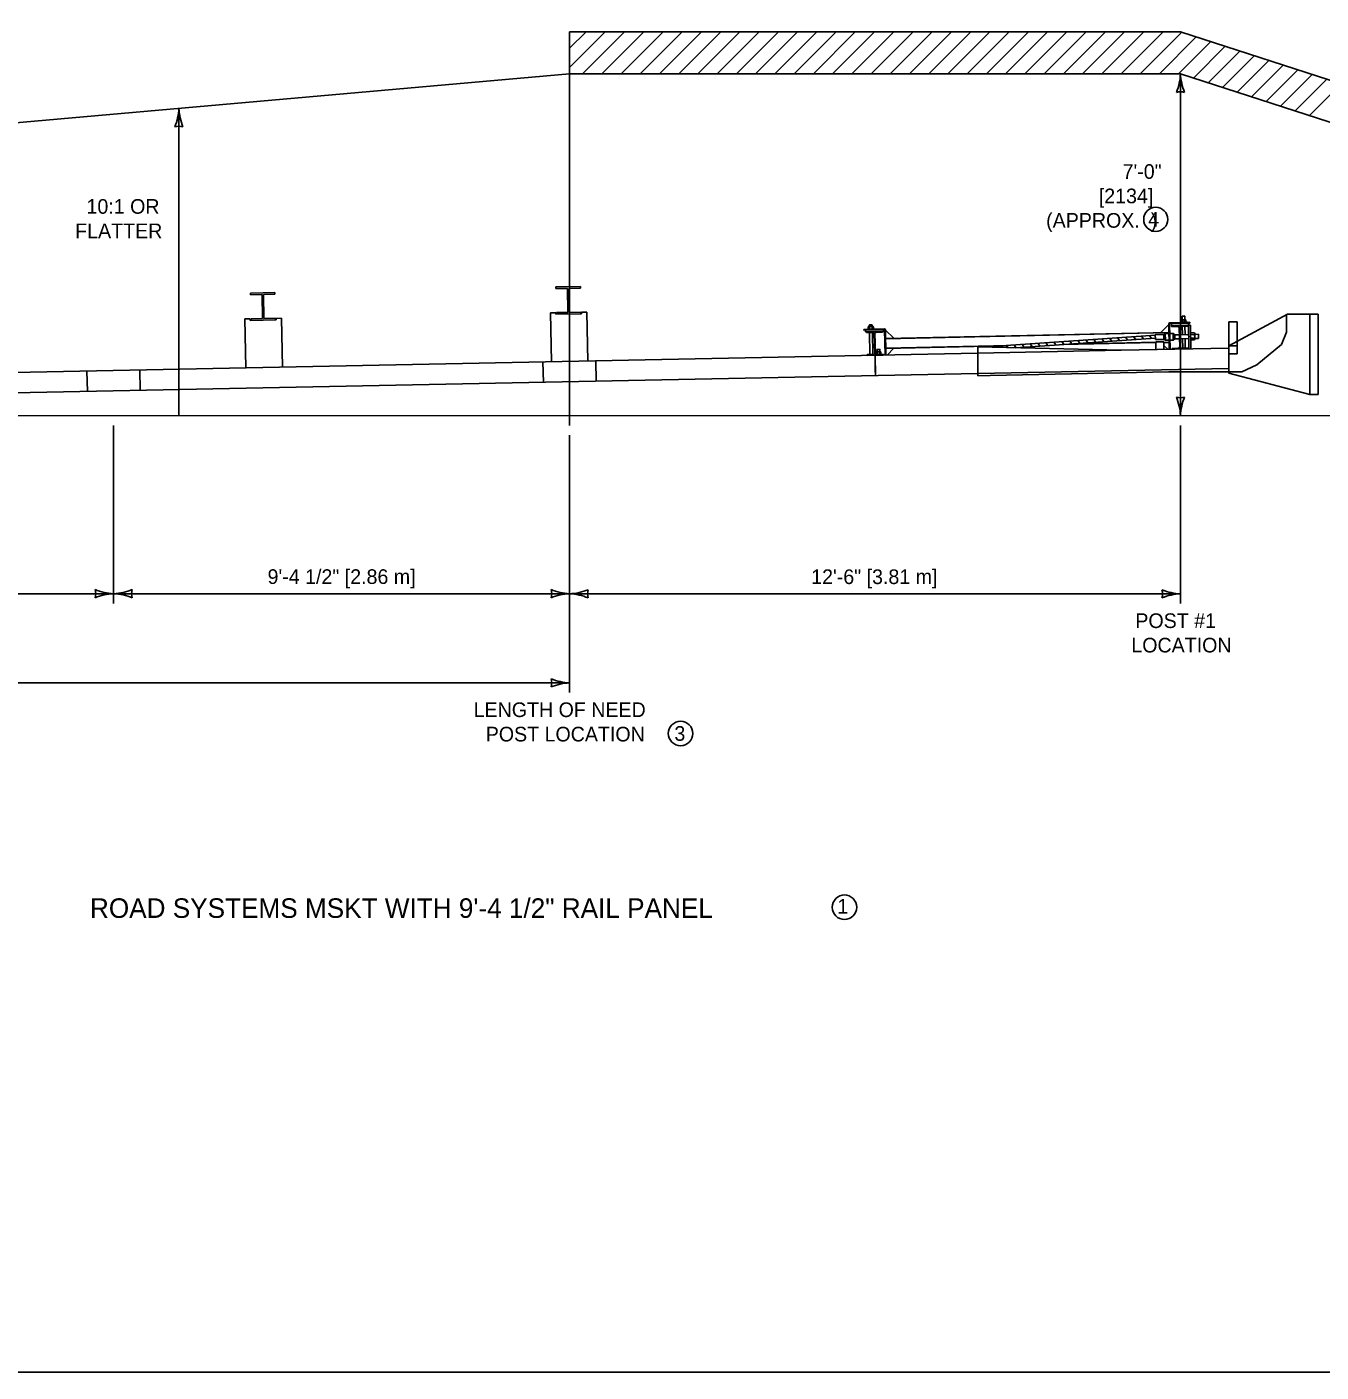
# Model space of a CAD drawing. Extents: x 49991.4 to 50021, y 49987.6 to 50011.4.
# Drawn here: x 50006.31 to 50011.61, y 49987.8 to 49993.3 of the extents above; entities that cross this region are included whole.
import ezdxf

# ---------------------------------------------------------------- set-up
doc = ezdxf.new("R2010")
doc.units = 0
for name, color, linetype in [('Level 1', 7, 'Continuous'), ('Level 2', 7, 'Continuous'), ('Level 3', 7, 'Continuous'), ('Level 5', 7, 'Continuous')]:
    doc.layers.add(name, color=color, linetype=linetype)

msp = doc.modelspace()

# ---------------------------------------------------------------- linework, layer by layer
at = {"layer": 'Level 1'}
for p, q in [((50011.0311, 49993.2847), (50008.5311, 49993.2847)), ((50008.5311, 49993.2847), (50008.5311, 49993.1129)), ((50008.6772, 49993.2847), (50008.5311, 49993.1386)), ((50008.5985, 49993.2847), (50008.5311, 49993.2173)), ((50008.7559, 49993.2847), (50008.5841, 49993.1129)), ((50008.8346, 49993.2847), (50008.6628, 49993.1129)), ((50008.9133, 49993.2847), (50008.7415, 49993.1129)), ((50008.992, 49993.2847), (50008.8202, 49993.1129)), ((50009.0707, 49993.2847), (50008.8989, 49993.1129)), ((50009.1494, 49993.2847), (50008.9776, 49993.1129)), ((50009.2281, 49993.2847), (50009.0563, 49993.1129)), ((50009.3068, 49993.2847), (50009.135, 49993.1129)), ((50009.3855, 49993.2847), (50009.2137, 49993.1129)), ((50009.4642, 49993.2847), (50009.2924, 49993.1129)), ((50009.5429, 49993.2847), (50009.3711, 49993.1129)), ((50009.6216, 49993.2847), (50009.4498, 49993.1129)), ((50009.7003, 49993.2847), (50009.5286, 49993.1129)), ((50009.779, 49993.2847), (50009.6073, 49993.1129)), ((50009.8577, 49993.2847), (50009.686, 49993.1129)), ((50009.9364, 49993.2847), (50009.7647, 49993.1129)), ((50010.0151, 49993.2847), (50009.8434, 49993.1129)), ((50010.0938, 49993.2847), (50009.9221, 49993.1129)), ((50010.1725, 49993.2847), (50010.0008, 49993.1129)), ((50010.2512, 49993.2847), (50010.0795, 49993.1129)), ((50010.3299, 49993.2847), (50010.1582, 49993.1129)), ((50010.4086, 49993.2847), (50010.2369, 49993.1129)), ((50010.4873, 49993.2847), (50010.3156, 49993.1129)), ((50010.5661, 49993.2847), (50010.3943, 49993.1129)), ((50010.6448, 49993.2847), (50010.473, 49993.1129)), ((50010.7235, 49993.2847), (50010.5517, 49993.1129)), ((50010.8022, 49993.2847), (50010.6304, 49993.1129)), ((50010.8809, 49993.2847), (50010.7091, 49993.1129)), ((50010.9596, 49993.2847), (50010.7878, 49993.1129)), ((50011.0365, 49993.2829), (50010.8665, 49993.1129)), ((50011.0959, 49993.2637), (50010.9451, 49993.1129)), ((50011.1552, 49993.2444), (50011.0236, 49993.1129)), ((50015.8765, 49991.7129), (50011.0311, 49993.2847)), ((50011.2144, 49993.2252), (50011.0848, 49993.0955)), ((50011.2738, 49993.206), (50011.1441, 49993.0763)), ((50011.3331, 49993.1867), (50011.2035, 49993.057)), ((50011.3924, 49993.1675), (50011.2628, 49993.0378)), ((50011.4518, 49993.1482), (50011.322, 49993.0186)), ((50011.5112, 49993.129), (50011.3814, 49992.9993)), ((50008.5311, 49993.1129), (50001.6559, 49992.504)), ((50011.0311, 49993.1129), (50008.5311, 49993.1129)), ((50015.3468, 49991.713), (50011.0311, 49993.1129)), ((50011.5704, 49993.1098), (50011.4407, 49992.98)), ((50011.6297, 49993.0905), (50011.5, 49992.9608)), ((50011.6891, 49993.0713), (50011.5594, 49992.9416)), ((50008.5749, 49992.2424), (50008.4752, 49992.2404)), ((50008.575, 49992.2356), (50008.5749, 49992.2424)), ((50007.3249, 49992.2174), (50007.2252, 49992.2154)), ((50007.2253, 49992.2086), (50007.2252, 49992.2154)), ((50007.2723, 49992.2095), (50007.2253, 49992.2086)), ((50007.2742, 49992.1112), (50007.2723, 49992.2095)), ((50007.325, 49992.2106), (50007.2781, 49992.2096)), ((50007.28, 49992.1113), (50007.2781, 49992.2096)), ((50007.325, 49992.2106), (50007.3249, 49992.2174)), ((50008.4753, 49992.2336), (50008.4752, 49992.2404)), ((50008.5223, 49992.2345), (50008.4753, 49992.2336)), ((50008.5242, 49992.1362), (50008.5223, 49992.2345)), ((50008.575, 49992.2356), (50008.5281, 49992.2346)), ((50008.53, 49992.1363), (50008.5281, 49992.2346)), ((50008.4523, 49992.1342), (50008.4742, 49992.1346)), ((50008.4523, 49992.1342), (50008.4563, 49991.9342)), ((50008.4742, 49992.1346), (50008.4743, 49992.1285)), ((50008.5242, 49992.1362), (50008.4773, 49992.1353)), ((50008.4774, 49992.1285), (50008.4773, 49992.1353)), ((50008.577, 49992.1373), (50008.53, 49992.1363)), ((50008.5771, 49992.1305), (50008.577, 49992.1373)), ((50008.58, 49992.1368), (50008.6018, 49992.1372)), ((50008.5801, 49992.1306), (50008.58, 49992.1368)), ((50008.6058, 49991.9372), (50008.6018, 49992.1372)), ((50007.2023, 49992.1092), (50007.2242, 49992.1096)), ((50007.2023, 49992.1092), (50007.2063, 49991.9092)), ((50007.2242, 49992.1096), (50007.2243, 49992.1035)), ((50007.3301, 49992.1056), (50007.2243, 49992.1035)), ((50007.2742, 49992.1112), (50007.2273, 49992.1103)), ((50007.2274, 49992.1035), (50007.2273, 49992.1103)), ((50007.327, 49992.1123), (50007.28, 49992.1113)), ((50007.3271, 49992.1055), (50007.327, 49992.1123)), ((50007.33, 49992.1118), (50007.3518, 49992.1122)), ((50007.3301, 49992.1056), (50007.33, 49992.1118)), ((50007.3558, 49991.9122), (50007.3518, 49992.1122)), ((50008.5801, 49992.1306), (50008.4743, 49992.1285)), ((50009.7528, 49992.0677), (50009.7526, 49992.0773)), ((50009.7716, 49992.0784), (50009.7553, 49992.0781)), ((50009.7582, 49992.0678), (50009.758, 49992.0774)), ((50009.7584, 49992.0853), (50009.7684, 49992.0855)), ((50009.7691, 49992.068), (50009.7689, 49992.0776)), ((50009.7745, 49992.0681), (50009.7743, 49992.0777)), ((50010.983, 49992.0866), (50010.9509, 49992.0538)), ((50010.985, 49991.9849), (50010.9829, 49992.0897)), ((50010.9861, 49992.0897), (50010.9882, 49991.985)), ((50010.987, 49992.0939), (50011.069, 49992.0955)), ((50010.9871, 49992.0908), (50011.069, 49992.0924)), ((50010.9945, 49992.0901), (50011.0634, 49992.0915)), ((50010.9947, 49992.0819), (50010.9945, 49992.0901)), ((50011.0636, 49992.0833), (50010.9947, 49992.0819)), ((50010.9947, 49992.0819), (50010.9947, 49992.0784)), ((50010.9947, 49992.0784), (50011.0204, 49992.0789)), ((50011.058, 49992.0969), (50011.0288, 49992.0964)), ((50011.0288, 49992.0948), (50011.0288, 49992.0964)), ((50011.0545, 49992.0952), (50011.0326, 49992.0948)), ((50011.0343, 49992.1048), (50011.0345, 49992.0972)), ((50011.0349, 49992.0792), (50011.0605, 49992.0797)), ((50011.0501, 49992.1058), (50011.0366, 49992.1055)), ((50011.0379, 49992.1205), (50011.0387, 49992.1214)), ((50011.0379, 49992.1205), (50011.0483, 49992.1206)), ((50011.0381, 49992.1056), (50011.0379, 49992.1205)), ((50011.0386, 49992.0793), (50011.0392, 49992.0452)), ((50011.0387, 49992.1214), (50011.0474, 49992.1215)), ((50011.0388, 49992.1049), (50011.039, 49992.0973)), ((50011.0388, 49992.1049), (50011.039, 49992.0981)), ((50011.0483, 49992.1206), (50011.0474, 49992.1215)), ((50011.0479, 49992.105), (50011.048, 49992.0975)), ((50011.0479, 49992.105), (50011.048, 49992.0983)), ((50011.0486, 49992.1057), (50011.0483, 49992.1206)), ((50011.0497, 49992.0454), (50011.0491, 49992.0795)), ((50011.0525, 49992.0976), (50011.0524, 49992.1051)), ((50011.058, 49992.0969), (50011.058, 49992.0953)), ((50011.0605, 49992.0797), (50011.0605, 49992.0832)), ((50011.0634, 49992.0915), (50011.0655, 49991.9865)), ((50011.0719, 49992.0843), (50011.0635, 49992.0841)), ((50011.069, 49992.0924), (50011.069, 49992.0955)), ((50011.0719, 49992.0843), (50011.0739, 49991.9866)), ((50011.469, 49992.1283), (50011.2292, 49991.9998)), ((50011.2626, 49992.0982), (50011.2292, 49992.0982)), ((50011.2292, 49992.0982), (50011.2292, 49991.8875)), ((50011.2626, 49991.967), (50011.2626, 49992.0982)), ((50011.4648, 49992.1261), (50011.4648, 49992.0549)), ((50011.5943, 49992.1283), (50011.469, 49992.1283)), ((50011.5608, 49991.8002), (50011.5608, 49992.1283)), ((50011.5943, 49991.8002), (50011.5943, 49992.1283)), ((50009.8192, 49992.0684), (50009.7357, 49992.0667)), ((50009.7358, 49992.0636), (50009.7357, 49992.0667)), ((50009.8193, 49992.0653), (50009.7358, 49992.0636)), ((50009.8161, 49992.0644), (50009.7419, 49992.0629)), ((50009.7419, 49992.0629), (50009.742, 49992.0568)), ((50009.742, 49992.0568), (50009.8162, 49992.0582)), ((50009.7463, 49992.0533), (50009.7462, 49992.0568)), ((50009.7463, 49992.0533), (50009.7744, 49992.0539)), ((50009.7593, 49991.9638), (50009.7577, 49992.0535)), ((50009.7702, 49992.0538), (50009.7719, 49991.9641)), ((50009.7778, 49992.0507), (50009.7795, 49991.9675)), ((50009.7823, 49991.9676), (50009.7807, 49992.0507)), ((50009.784, 49992.0541), (50009.8121, 49992.0546)), ((50009.812, 49992.0582), (50009.8121, 49992.0546)), ((50009.8161, 49992.0644), (50009.8162, 49992.0582)), ((50009.8224, 49991.9615), (50009.8204, 49992.0643)), ((50009.8256, 49991.9615), (50009.8235, 49992.0643)), ((50009.8235, 49992.0633), (50009.8584, 49992.0304)), ((50010.9836, 49992.0545), (50009.8242, 49992.0297)), ((50010.9836, 49992.0534), (50009.8242, 49992.0285)), ((50010.238, 49991.9947), (50010.9289, 49992.0433)), ((50010.3577, 49991.9917), (50010.9288, 49992.031)), ((50010.6435, 49992.0232), (50010.6517, 49992.012)), ((50010.676, 49992.0255), (50010.6843, 49992.0142)), ((50010.7086, 49992.0278), (50010.7169, 49992.0164)), ((50010.7411, 49992.0301), (50010.7495, 49992.0187)), ((50010.7737, 49992.0324), (50010.7821, 49992.0209)), ((50010.8063, 49992.0347), (50010.8147, 49992.0232)), ((50010.8388, 49992.037), (50010.8473, 49992.0254)), ((50010.8714, 49992.0393), (50010.8799, 49992.0276)), ((50010.904, 49992.0416), (50010.9125, 49992.0299)), ((50010.9278, 49992.0456), (50010.9628, 49992.0461)), ((50010.9278, 49992.0456), (50010.9282, 49992.0251)), ((50010.969, 49992.0491), (50010.9628, 49992.0461)), ((50010.9628, 49992.0461), (50010.9632, 49992.0256)), ((50010.969, 49992.0491), (50010.9837, 49992.0493)), ((50010.9694, 49992.0224), (50010.969, 49992.0491)), ((50010.9694, 49992.0224), (50010.9843, 49992.0227)), ((50011.0014, 49992.0497), (50010.9869, 49992.0494)), ((50011.0017, 49992.023), (50010.9874, 49992.0228)), ((50011.0077, 49992.0446), (50011.0014, 49992.0497)), ((50011.0014, 49992.0497), (50011.0017, 49992.023)), ((50011.0079, 49992.0282), (50011.0017, 49992.023)), ((50011.0077, 49992.0446), (50011.0269, 49992.045)), ((50011.0077, 49992.0446), (50011.0079, 49992.0282)), ((50011.0079, 49992.0282), (50011.0272, 49992.0286)), ((50011.0263, 49992.0733), (50011.0279, 49991.995)), ((50011.0308, 49991.9951), (50011.0292, 49992.0734)), ((50011.0297, 49992.045), (50011.0643, 49992.0457)), ((50011.0301, 49992.0286), (50011.0647, 49992.0293)), ((50011.0395, 49992.0288), (50011.0403, 49991.9895)), ((50011.0507, 49991.9898), (50011.05, 49992.029)), ((50011.0725, 49992.052), (50011.0881, 49992.0523)), ((50011.0727, 49992.0449), (50011.0882, 49992.0452)), ((50011.073, 49992.0305), (50011.0884, 49992.0308)), ((50011.0731, 49992.0233), (50011.0886, 49992.0236)), ((50011.0892, 49992.0488), (50011.0896, 49992.0272)), ((50011.1044, 49992.0464), (50011.0893, 49992.0461)), ((50011.1046, 49992.03), (50011.0895, 49992.0297)), ((50011.1044, 49992.0464), (50011.1047, 49992.03)), ((50011.4648, 49992.0549), (50011.4451, 49992.0052)), ((50001.6561, 49991.7982), (50010.202, 49991.9692)), ((50009.7867, 49991.9644), (50009.7865, 49991.9741)), ((50009.8025, 49991.975), (50009.7888, 49991.9748)), ((50009.7913, 49991.9645), (50009.7911, 49991.9742)), ((50009.8004, 49991.9647), (50009.8002, 49991.9744)), ((50009.805, 49991.9647), (50009.8048, 49991.9744)), ((50010.3292, 49992.0011), (50009.825, 49991.9898)), ((50010.3052, 49991.9994), (50009.825, 49991.9887)), ((50009.8305, 49991.9616), (50009.8577, 49991.9894)), ((50010.202, 49991.9956), (50010.202, 49991.876)), ((50010.788, 49991.9809), (50010.202, 49991.9956)), ((50010.788, 49991.9809), (50010.202, 49991.9692)), ((50010.2345, 49991.9955), (50010.2201, 49991.9952)), ((50010.2345, 49991.9948), (50010.2345, 49991.9955)), ((50010.2527, 49991.9958), (50010.2538, 49991.9943)), ((50010.2853, 49991.998), (50010.2886, 49991.9935)), ((50010.3178, 49992.0003), (50010.3235, 49991.9926)), ((50010.3504, 49992.0026), (50010.3583, 49991.9918)), ((50010.383, 49992.0049), (50010.3909, 49991.994)), ((50010.4155, 49992.0072), (50010.4235, 49991.9963)), ((50010.4481, 49992.0095), (50010.4561, 49991.9985)), ((50010.4806, 49992.0118), (50010.4887, 49992.0007)), ((50010.5132, 49992.0141), (50010.5213, 49992.003)), ((50010.5458, 49992.0164), (50010.5539, 49992.0052)), ((50010.9301, 49992.0134), (50010.5494, 49992.0049)), ((50010.9301, 49992.0146), (50010.5742, 49992.0066)), ((50010.5783, 49992.0187), (50010.5865, 49992.0075)), ((50010.6109, 49992.021), (50010.6191, 49992.0097)), ((50010.788, 49991.9809), (50011.2292, 49991.9898)), ((50010.9296, 49992.0159), (50010.963, 49992.0161)), ((50010.9298, 49991.9838), (50010.9296, 49992.0159)), ((50010.9632, 49991.9845), (50010.963, 49992.0161)), ((50010.9844, 49992.0139), (50010.963, 49992.0135)), ((50010.9845, 49992.0128), (50010.963, 49992.0124)), ((50010.98, 49991.9848), (50010.9631, 49992.0008)), ((50011.0222, 49991.9892), (50010.9965, 49991.9887)), ((50010.9965, 49991.9887), (50010.9966, 49991.9851)), ((50011.0655, 49991.9865), (50010.9966, 49991.9851)), ((50011.0624, 49991.99), (50011.0367, 49991.9895)), ((50011.0624, 49991.9865), (50011.0624, 49991.99)), ((50011.2292, 49991.9998), (50011.2626, 49991.9998)), ((50011.2292, 49991.967), (50011.2626, 49991.967)), ((50011.4451, 49992.0052), (50011.3437, 49991.9215)), ((50008.4219, 49991.9336), (50008.4236, 49991.8498)), ((50008.6385, 49991.9379), (50008.6402, 49991.8541)), ((50009.7481, 49991.9636), (50009.7762, 49991.9642)), ((50009.7481, 49991.9636), (50009.7482, 49991.9601)), ((50009.814, 49991.9614), (50009.7482, 49991.9601)), ((50009.7827, 49991.877), (50009.7811, 49991.9607)), ((50009.7821, 49991.8913), (50009.7817, 49991.9464)), ((50009.7858, 49991.9644), (50009.8139, 49991.9649)), ((50009.814, 49991.9614), (50009.8139, 49991.9649)), ((50011.3437, 49991.9215), (50011.2827, 49991.8924)), ((50001.6561, 49991.7144), (50010.202, 49991.8854)), ((50006.5557, 49991.8962), (50006.5574, 49991.8125)), ((50006.7723, 49991.9006), (50006.774, 49991.8168)), ((50011.2273, 49991.906), (50010.202, 49991.8854)), ((50010.2519, 49991.8772), (50010.202, 49991.876)), ((50010.2519, 49991.8772), (50010.9828, 49991.8924)), ((50010.9828, 49991.8924), (50011.2292, 49991.8924)), ((50011.2827, 49991.8924), (50011.2292, 49991.8924)), ((50011.2292, 49991.8875), (50011.5608, 49991.8002)), ((50011.5608, 49991.8002), (50011.5943, 49991.8002)), ((50000.2381, 49991.7144), (50015.8765, 49991.7129))]:
    msp.add_line(p, q, dxfattribs=at)
msp.add_lwpolyline([(49999.3835, 49998.9992), (50016.7501, 49998.9992), (50016.7501, 49987.7988), (49999.3835, 49987.7988)], close=True, dxfattribs=at)
for points in [[(50009.7584, 49992.0853), (50009.7571, 49992.0841), (50009.7572, 49992.0781)], [(50009.7684, 49992.0855), (50009.7697, 49992.0843), (50009.7698, 49992.0783)], [(50010.9694, 49992.0224), (50010.9632, 49992.0256), (50010.9282, 49992.0251)], [(50009.7904, 49991.9748), (50009.7903, 49991.9841), (50009.8007, 49991.9843), (50009.8009, 49991.975)]]:
    msp.add_lwpolyline(points, dxfattribs=at)
for centre, major_axis, start_param, end_param in [((50009.7554, 49992.0729), (-0.00527, -0.0001), 4.171739, 5.253075), ((50009.7638, 49992.0586), (-0.02, -0.0004), 4.437003, 4.987775), ((50009.7717, 49992.0732), (-0.00527, -0.0001), 4.171554, 5.253188), ((50010.9871, 49992.0898), (-0.00418, -0.00008), 4.714257, 6.285053), ((50010.9871, 49992.0898), (-0.00104, -0.00002), 4.714257, 6.285053), ((50011.0205, 49992.0732), (-0.0058, -0.00011), 3.143461, 4.714257), ((50011.035, 49992.0735), (-0.0058, -0.00011), 4.714257, 6.285053), ((50011.0366, 49992.1017), (-0.00386, -0.00007), 4.086959, 5.337819), ((50011.0367, 49992.1003), (-0.00386, -0.00007), 0.945366, 2.196226), ((50011.0436, 49992.0916), (-0.0143, -0.0003), 4.391838, 5.03294), ((50011.0433, 49992.1108), (-0.0143, -0.0003), 1.250246, 1.891347), ((50011.0502, 49992.102), (-0.00386, -0.00007), 4.086957, 5.337821), ((50011.0502, 49992.1006), (-0.00386, -0.00007), 0.945365, 2.196228), ((50009.7554, 49992.0722), (0.00527, 0.0001), 4.171703, 5.253039), ((50009.7633, 49992.0868), (0.02, 0.0004), 4.437003, 4.987775), ((50009.7717, 49992.0725), (0.00527, 0.0001), 4.17159, 5.253224), ((50009.7745, 49992.0506), (-0.00334, -0.00006), 3.143461, 4.714257), ((50009.784, 49992.0508), (-0.00334, -0.00006), 4.714257, 6.285053), ((50009.8193, 49992.0643), (-0.00418, -0.00008), 3.143461, 4.714257), ((50009.8193, 49992.0643), (-0.00104, -0.00002), 3.143461, 4.714257), ((50011.0821, 49992.0486), (0.00707, 0.00013), 5.740021, 6.82635), ((50011.0626, 49992.0375), (0.0267, 0.0005), 6.006504, 6.559866), ((50011.0825, 49992.0271), (0.00707, 0.00013), 5.740021, 6.82635), ((50009.7762, 49991.9675), (-0.00334, -0.00006), 1.572665, 3.143461), ((50009.7857, 49991.9676), (-0.00334, -0.00006), 0.001868, 1.572665), ((50009.7889, 49991.9705), (-0.00433, -0.00008), 4.157119, 5.267659), ((50009.7959, 49991.9589), (-0.0164, -0.0003), 4.429299, 4.995479), ((50009.8026, 49991.9708), (-0.00433, -0.00008), 4.157119, 5.267659), ((50011.0221, 49991.9949), (-0.0058, -0.00011), 1.572665, 3.143461), ((50011.0366, 49991.9952), (-0.0058, -0.00011), 0.001868, 1.572665)]:
    msp.add_ellipse(centre, major_axis=major_axis, ratio=0.981938, start_param=start_param, end_param=end_param, dxfattribs=at)
at = {"layer": 'Level 2'}
for centre, radius in [((50010.9297, 49992.517), 0.0492), ((50008.985, 49990.4127), 0.05), ((50009.6559, 49989.7016), 0.05)]:
    msp.add_circle(centre, radius, dxfattribs=at)
at = {"layer": 'Level 3'}
for p, q in [((50011.0311, 49993.1129), (50011.0311, 49991.7135)), ((50006.9319, 49992.9713), (50006.9319, 49991.7139)), ((50006.6649, 49990.9447), (50006.6649, 49991.6738)), ((50011.031, 49990.9443), (50011.031, 49991.6734)), ((50008.531, 49990.9447), (50008.531, 49991.6337)), ((50008.531, 49990.5799), (50008.531, 49991.3088)), ((50006.6649, 49990.9847), (50004.1649, 49990.9847)), ((50008.531, 49990.9847), (50006.6649, 49990.9847)), ((50011.031, 49990.9843), (50008.531, 49990.9843)), ((50008.531, 49990.6199), (50001.6561, 49990.6199))]:
    msp.add_line(p, q, dxfattribs=at)
for centre, radius, start, end in [((50010.8089, 49993.1221), 0.2223, 337.456, 357.6395), ((50011.2638, 49993.1244), 0.233, 182.8273, 202.0772), ((50011.0311, 49992.9847), 0.0548, 72.1388, 107.8612), ((50006.7097, 49992.9805), 0.2223, 337.456, 357.6395), ((50007.1646, 49992.9828), 0.233, 182.8273, 202.0772), ((50006.9319, 49992.8431), 0.0548, 72.1388, 107.8612), ((50011.0311, 49991.8417), 0.0548, 252.1388, 287.8612), ((50010.7983, 49991.702), 0.233, 2.8273, 22.0772), ((50011.2532, 49991.7043), 0.2223, 157.456, 177.6395), ((50006.674, 49991.2069), 0.2223, 247.456, 267.6395), ((50006.5366, 49990.9847), 0.0548, 342.1388, 17.8612), ((50006.6763, 49990.752), 0.233, 92.8273, 112.0772), ((50006.6534, 49991.2174), 0.233, 272.8273, 292.0772), ((50006.6557, 49990.7626), 0.2223, 67.456, 87.6395), ((50006.7931, 49990.9847), 0.0548, 162.1388, 197.8612), ((50008.5402, 49991.2069), 0.2223, 247.456, 267.6395), ((50008.4028, 49990.9847), 0.0548, 342.1388, 17.8612), ((50008.5425, 49990.752), 0.233, 92.8273, 112.0772), ((50008.5195, 49991.217), 0.233, 272.8273, 292.0772), ((50008.5219, 49990.7622), 0.2223, 67.456, 87.6395), ((50008.6593, 49990.9843), 0.0548, 162.1388, 197.8612), ((50011.0402, 49991.2064), 0.2223, 247.456, 267.6395), ((50010.9028, 49990.9843), 0.0548, 342.1388, 17.8612), ((50011.0425, 49990.7516), 0.233, 92.8273, 112.0772), ((50008.5402, 49990.8421), 0.2223, 247.456, 267.6395), ((50008.4028, 49990.6199), 0.0548, 342.1388, 17.8612), ((50008.5425, 49990.3872), 0.233, 92.8273, 112.0772)]:
    msp.add_arc(centre, radius, start, end, dxfattribs=at)
at = {"layer": 'Level 5'}
msp.add_line((50008.5311, 49993.1129), (50008.531, 49991.6737), dxfattribs=at)

# ---------------------------------------------------------------- texts
at = {"layer": 'Level 2'}
for s, height, p in [('7\'-0"', 0.06, (50010.7941, 49992.6828)), ('[2134]', 0.06, (50010.6967, 49992.5828)), ('10:1 OR', 0.06, (50006.5539, 49992.5399)), ('(APPROX.  )', 0.06, (50010.4812, 49992.4828)), ('4', 0.06, (50010.899, 49992.4865)), ('FLATTER', 0.06, (50006.5075, 49992.4399)), ('9\'-4 1/2" [2.86 m]', 0.06, (50007.2949, 49991.0247)), ('12\'-6" [3.81 m]', 0.06, (50009.5198, 49991.0243)), ('POST #1', 0.06, (50010.8463, 49990.8443)), ('LOCATION', 0.06, (50010.8299, 49990.7443)), ('LENGTH OF NEED', 0.06, (50008.1382, 49990.4799)), ('POST LOCATION', 0.06, (50008.1878, 49990.38)), ('3', 0.06, (50008.9598, 49990.3827)), ('ROAD SYSTEMS MSKT WITH 9\'-4 1/2" RAIL PANEL', 0.08, (50006.5681, 49989.6579)), ('1', 0.06, (50009.6266, 49989.6752))]:
    msp.add_text(s, height=height, dxfattribs=at).set_placement(p)

doc.saveas('drawing.dxf')
